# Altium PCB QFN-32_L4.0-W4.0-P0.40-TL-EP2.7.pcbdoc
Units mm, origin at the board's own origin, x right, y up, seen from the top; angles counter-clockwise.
Board outline 17.62 x 17.62 mm, 2 copper layers (Top Layer, Bottom Layer), stack 0 mm thick; 1 components, 0 nets, 33 pads, 0 vias.
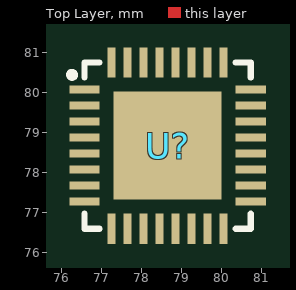
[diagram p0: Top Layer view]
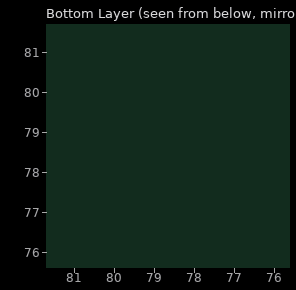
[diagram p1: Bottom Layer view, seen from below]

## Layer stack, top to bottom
Top Layer: signal copper (thickness not stored)
Bottom Layer: signal copper (thickness not stored)

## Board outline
87.475,69.85 69.85,69.85 69.85,87.47 87.475,87.47

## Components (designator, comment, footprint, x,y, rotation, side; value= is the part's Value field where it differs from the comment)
U? "" QFN-32_L4.0-W4.0-P0.40-TL-EP2.7 78.665,78.66 r0 top

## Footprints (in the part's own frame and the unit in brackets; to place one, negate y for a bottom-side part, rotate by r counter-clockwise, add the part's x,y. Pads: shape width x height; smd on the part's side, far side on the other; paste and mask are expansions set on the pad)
QFN-32_L4.0-W4.0-P0.40-TL-EP2.7 [mm]
  rect 0.76x0.2 smd paste-100 mask+0.051: 1(-2.08,1.4) 2(-2.08,1) 3(-2.08,0.6) 4(-2.08,0.2) 5(-2.08,-0.2) 6(-2.08,-0.6) 7(-2.08,-1) 8(-2.08,-1.4) 17(2.08,-1.4) 18(2.08,-1) 19(2.08,-0.6) 20(2.08,-0.2) 21(2.08,0.2) 22(2.08,0.6) 23(2.08,1) 24(2.08,1.4)
  rect 0.2x0.76 smd paste-100 mask+0.051: 9(-1.4,-2.08) 10(-1,-2.08) 11(-0.6,-2.08) 12(-0.2,-2.08) 13(0.2,-2.08) 14(0.6,-2.08) 15(1,-2.08) 16(1.4,-2.08) 25(1.4,2.08) 26(1,2.08) 27(0.6,2.08) 28(0.2,2.08) 29(-0.2,2.08) 30(-0.6,2.08) 31(-1,2.08) 32(-1.4,2.08)
  rect 2.7x2.7 smd paste-100 mask+0.051: 33(0,0)
  silkscreen extent -2.46,-2.08 2.08,2.08

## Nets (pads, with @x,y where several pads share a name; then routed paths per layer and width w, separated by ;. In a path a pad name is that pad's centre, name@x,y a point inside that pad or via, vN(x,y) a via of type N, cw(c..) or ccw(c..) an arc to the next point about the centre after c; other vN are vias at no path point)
pads on no net: U?.1 U?.2 U?.3 U?.4 U?.5 U?.6 U?.7 U?.8 U?.9 U?.10 U?.11 U?.12 U?.13 U?.14 U?.15 U?.16 U?.17 U?.18 U?.19 U?.20 U?.21 U?.22 U?.23 U?.24 U?.25 U?.26 U?.27 U?.28 U?.29 U?.30 U?.31 U?.32 U?.33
